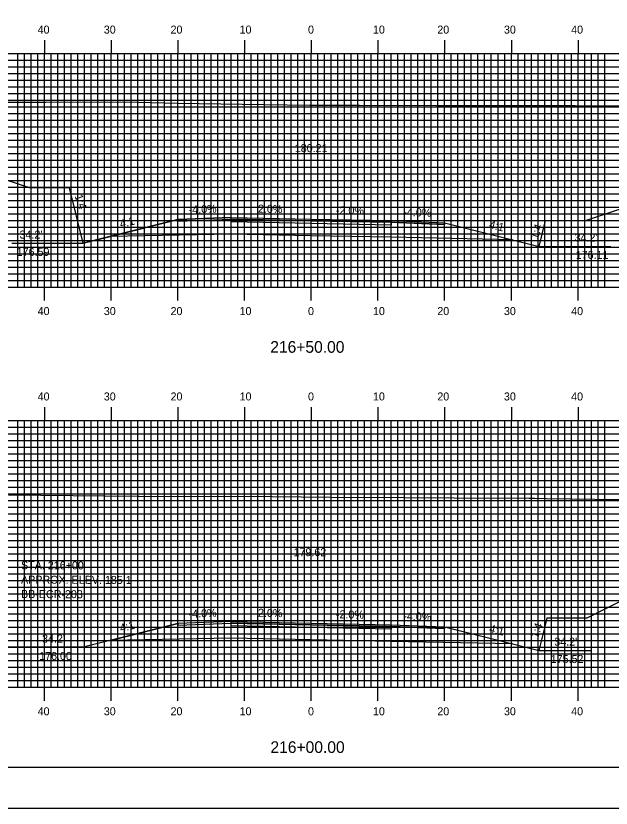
# Model space of a CAD drawing. Extents: x 1796420 to 1796763, y 442591 to 442811.
# Drawn here: x 1796541.6 to 1796630.9, y 442590.5 to 442709.3 of the extents above; entities that cross this region are included whole.
import ezdxf

# ---------------------------------------------------------------- set-up
doc = ezdxf.new("R2010")
doc.units = 0
for name, color, linetype in [('ANNOTATION', 7, 'Continuous'), ('BORDER', 7, 'Continuous'), ('BORING - REFUSAL', 7, 'Continuous'), ('D_Roadway_Centerline', 7, 'Continuous'), ('D_Roadway_Centerline_Text', 7, 'Continuous'), ('D_Roadway_Edge_Shoulder', 7, 'Continuous'), ('D_Roadway_Edge_TW', 7, 'Continuous'), ('D_Roadway_Pavement', 7, 'Continuous'), ('D_Roadway_SlopeLines', 7, 'Continuous'), ('D_Roadway_SubGrade', 7, 'Continuous'), ('H_V ANNOTATION', 7, 'Continuous'), ('MAJOR', 7, 'Continuous'), ('MINOR', 7, 'Continuous'), ('PDRAIN', 7, 'Continuous'), ('PLOT BOUNDARY', 7, 'Continuous'), ('S_Roadway_Centerline', 7, 'Continuous')]:
    doc.layers.add(name, color=color, linetype=linetype)

msp = doc.modelspace()

# ---------------------------------------------------------------- linework, layer by layer
at = {"layer": 'ANNOTATION'}
for p, q in [((1796620.08, 442674.77), (1796621.05, 442678.67)), ((1796620.08, 442614.19), (1796621.08, 442618.19)), ((1796551.73, 442614.67), (1796529.31, 442614.67))]:
    msp.add_line(p, q, dxfattribs=at)
at = {"layer": 'BORDER'}
msp.add_lwpolyline([(1796436.31, 442596.67), (1796756.31, 442596.67), (1796756.31, 442806.67), (1796436.31, 442806.67)], close=True, dxfattribs=at)
at = {"layer": 'D_Roadway_Centerline'}
msp.add_lwpolyline([(1796551.73, 442675.25), (1796555.73, 442676.25), (1796565.91, 442678.79), (1796573.91, 442679.11), (1796585.91, 442678.87), (1796597.91, 442678.63), (1796605.91, 442678.31), (1796616.08, 442675.77), (1796620.08, 442674.77)], dxfattribs=at)
at = {"layer": 'D_Roadway_Edge_Shoulder'}
for points in [[(1796573.91, 442679.11), (1796565.91, 442678.79), (1796565.91, 442678.54), (1796573.91, 442678.86)], [(1796597.91, 442678.63), (1796605.91, 442678.31), (1796605.91, 442678.06), (1796597.91, 442678.38)], [(1796573.91, 442618.53), (1796565.91, 442618.21), (1796565.91, 442617.96), (1796573.91, 442618.28)], [(1796597.91, 442618.05), (1796605.91, 442617.73), (1796605.91, 442617.48), (1796597.91, 442617.8)]]:
    msp.add_lwpolyline(points, close=True, dxfattribs=at)
at = {"layer": 'D_Roadway_Edge_TW'}
for points in [[(1796573.91, 442678.86), (1796573.91, 442679.11), (1796585.91, 442678.87), (1796597.91, 442678.63), (1796597.91, 442678.38), (1796585.91, 442678.62)], [(1796573.91, 442618.28), (1796573.91, 442618.53), (1796585.91, 442618.29), (1796597.91, 442618.05), (1796597.91, 442617.8), (1796585.91, 442618.04)]]:
    msp.add_lwpolyline(points, close=True, dxfattribs=at)
at = {"layer": 'D_Roadway_Pavement'}
for points in [[(1796573.91, 442678.45), (1796573.91, 442678.86), (1796585.91, 442678.62), (1796597.91, 442678.38), (1796597.91, 442677.97), (1796585.91, 442678.21)], [(1796573.91, 442617.86), (1796573.91, 442618.28), (1796585.91, 442618.04), (1796597.91, 442617.8), (1796597.91, 442617.38), (1796585.91, 442617.62)]]:
    msp.add_lwpolyline(points, close=True, dxfattribs=at)
at = {"layer": 'D_Roadway_SlopeLines'}
msp.add_line((1796551.73, 442675.25), (1796549.65, 442683.57), dxfattribs=at)
for points in [[(1796549.65, 442683.57), (1796543.65, 442683.57), (1796505.9, 442696.15)], [(1796621.05, 442678.67), (1796627.05, 442678.67), (1796674.72, 442694.55)], [(1796565.91, 442678.79), (1796551.73, 442675.25)], [(1796605.91, 442678.31), (1796620.08, 442674.77)], [(1796621.3, 442619.07), (1796627.3, 442619.07), (1796660.02, 442635.43)], [(1796565.91, 442618.21), (1796551.73, 442614.67)], [(1796605.91, 442617.73), (1796620.08, 442614.19)]]:
    msp.add_lwpolyline(points, dxfattribs=at)
at = {"layer": 'D_Roadway_SubGrade'}
msp.add_line((1796621.08, 442618.19), (1796621.3, 442619.07), dxfattribs=at)
for points in [[(1796573.91, 442676.61), (1796555.73, 442676.25), (1796565.91, 442678.79), (1796565.91, 442678.54), (1796573.91, 442678.86), (1796585.91, 442678.62), (1796597.91, 442678.38), (1796605.91, 442678.06), (1796605.91, 442678.31), (1796616.08, 442675.77), (1796597.91, 442676.13), (1796585.91, 442676.37)], [(1796573.91, 442616.03), (1796555.73, 442615.67), (1796565.91, 442618.21), (1796565.91, 442617.96), (1796573.91, 442618.28), (1796585.91, 442618.04), (1796597.91, 442617.8), (1796605.91, 442617.48), (1796605.91, 442617.73), (1796616.08, 442615.19), (1796597.91, 442615.55), (1796585.91, 442615.79)]]:
    msp.add_lwpolyline(points, close=True, dxfattribs=at)
at = {"layer": 'MAJOR'}
for p, q in [((1796545.91, 442705.67), (1796545.91, 442703.67)), ((1796555.91, 442705.67), (1796555.91, 442703.67)), ((1796565.91, 442705.67), (1796565.91, 442703.67)), ((1796575.91, 442705.67), (1796575.91, 442703.67)), ((1796585.91, 442705.67), (1796585.91, 442703.67)), ((1796595.91, 442705.67), (1796595.91, 442703.67)), ((1796605.91, 442705.67), (1796605.91, 442703.67)), ((1796615.91, 442705.67), (1796615.91, 442703.67)), ((1796625.91, 442705.67), (1796625.91, 442703.67)), ((1796445.91, 442703.67), (1796725.91, 442703.67)), ((1796445.91, 442703.67), (1796725.91, 442703.67)), ((1796545.91, 442668.67), (1796545.91, 442703.67)), ((1796555.91, 442668.67), (1796555.91, 442703.67)), ((1796565.91, 442668.67), (1796565.91, 442703.67)), ((1796575.91, 442668.67), (1796575.91, 442703.67)), ((1796585.91, 442668.67), (1796585.91, 442703.67)), ((1796595.91, 442668.67), (1796595.91, 442703.67)), ((1796605.91, 442668.67), (1796605.91, 442703.67)), ((1796615.91, 442668.67), (1796615.91, 442703.67)), ((1796625.91, 442668.67), (1796625.91, 442703.67)), ((1796445.91, 442698.67), (1796725.91, 442698.67)), ((1796445.91, 442693.67), (1796725.91, 442693.67)), ((1796445.91, 442688.67), (1796725.91, 442688.67)), ((1796445.91, 442683.67), (1796725.91, 442683.67)), ((1796445.91, 442678.67), (1796725.91, 442678.67)), ((1796445.91, 442673.67), (1796725.91, 442673.67)), ((1796445.91, 442668.67), (1796725.91, 442668.67)), ((1796445.91, 442668.67), (1796725.91, 442668.67)), ((1796545.91, 442666.66), (1796545.91, 442668.67)), ((1796555.91, 442666.66), (1796555.91, 442668.67)), ((1796565.91, 442666.66), (1796565.91, 442668.67)), ((1796575.91, 442666.66), (1796575.91, 442668.67)), ((1796585.91, 442666.66), (1796585.91, 442668.67)), ((1796595.91, 442666.66), (1796595.91, 442668.67)), ((1796605.91, 442666.66), (1796605.91, 442668.67)), ((1796615.91, 442666.66), (1796615.91, 442668.67)), ((1796625.91, 442666.66), (1796625.91, 442668.67)), ((1796545.91, 442650.67), (1796545.91, 442648.67)), ((1796555.91, 442650.67), (1796555.91, 442648.67)), ((1796565.91, 442650.67), (1796565.91, 442648.67)), ((1796575.91, 442650.67), (1796575.91, 442648.67)), ((1796585.91, 442650.67), (1796585.91, 442648.67)), ((1796595.91, 442650.67), (1796595.91, 442648.67)), ((1796605.91, 442650.67), (1796605.91, 442648.67)), ((1796615.91, 442650.67), (1796615.91, 442648.67)), ((1796625.91, 442650.67), (1796625.91, 442648.67)), ((1796445.91, 442648.67), (1796725.91, 442648.67)), ((1796445.91, 442648.67), (1796725.91, 442648.67)), ((1796545.91, 442608.67), (1796545.91, 442648.67)), ((1796555.91, 442608.67), (1796555.91, 442648.67)), ((1796565.91, 442608.67), (1796565.91, 442648.67)), ((1796575.91, 442608.67), (1796575.91, 442648.67)), ((1796585.91, 442608.67), (1796585.91, 442648.67)), ((1796595.91, 442608.67), (1796595.91, 442648.67)), ((1796605.91, 442608.67), (1796605.91, 442648.67)), ((1796615.91, 442608.67), (1796615.91, 442648.67)), ((1796625.91, 442608.67), (1796625.91, 442648.67)), ((1796445.91, 442643.67), (1796725.91, 442643.67)), ((1796445.91, 442638.67), (1796725.91, 442638.67)), ((1796445.91, 442633.67), (1796725.91, 442633.67)), ((1796445.91, 442628.67), (1796725.91, 442628.67)), ((1796445.91, 442623.67), (1796725.91, 442623.67)), ((1796445.91, 442618.67), (1796725.91, 442618.67)), ((1796445.91, 442613.67), (1796725.91, 442613.67)), ((1796445.91, 442608.67), (1796725.91, 442608.67)), ((1796445.91, 442608.67), (1796725.91, 442608.67)), ((1796545.91, 442606.66), (1796545.91, 442608.67)), ((1796555.91, 442606.66), (1796555.91, 442608.67)), ((1796565.91, 442606.66), (1796565.91, 442608.67)), ((1796575.91, 442606.66), (1796575.91, 442608.67)), ((1796585.91, 442606.66), (1796585.91, 442608.67)), ((1796595.91, 442606.66), (1796595.91, 442608.67)), ((1796605.91, 442606.66), (1796605.91, 442608.67)), ((1796615.91, 442606.66), (1796615.91, 442608.67)), ((1796625.91, 442606.66), (1796625.91, 442608.67))]:
    msp.add_line(p, q, dxfattribs=at)
at = {"layer": 'MINOR'}
for p, q in [((1796445.91, 442702.67), (1796725.91, 442702.67)), ((1796541.91, 442668.67), (1796541.91, 442703.67)), ((1796542.91, 442668.67), (1796542.91, 442703.67)), ((1796543.91, 442668.67), (1796543.91, 442703.67)), ((1796544.91, 442668.67), (1796544.91, 442703.67)), ((1796546.91, 442668.67), (1796546.91, 442703.67)), ((1796547.91, 442668.67), (1796547.91, 442703.67)), ((1796548.91, 442668.67), (1796548.91, 442703.67)), ((1796549.91, 442668.67), (1796549.91, 442703.67)), ((1796550.91, 442668.67), (1796550.91, 442703.67)), ((1796551.91, 442668.67), (1796551.91, 442703.67)), ((1796552.91, 442668.67), (1796552.91, 442703.67)), ((1796553.91, 442668.67), (1796553.91, 442703.67)), ((1796554.91, 442668.67), (1796554.91, 442703.67)), ((1796556.91, 442668.67), (1796556.91, 442703.67)), ((1796557.91, 442668.67), (1796557.91, 442703.67)), ((1796558.91, 442668.67), (1796558.91, 442703.67)), ((1796559.91, 442668.67), (1796559.91, 442703.67)), ((1796560.91, 442668.67), (1796560.91, 442703.67)), ((1796561.91, 442668.67), (1796561.91, 442703.67)), ((1796562.91, 442668.67), (1796562.91, 442703.67)), ((1796563.91, 442668.67), (1796563.91, 442703.67)), ((1796564.91, 442668.67), (1796564.91, 442703.67)), ((1796566.91, 442668.67), (1796566.91, 442703.67)), ((1796567.91, 442668.67), (1796567.91, 442703.67)), ((1796568.91, 442668.67), (1796568.91, 442703.67)), ((1796569.91, 442668.67), (1796569.91, 442703.67)), ((1796570.91, 442668.67), (1796570.91, 442703.67)), ((1796571.91, 442668.67), (1796571.91, 442703.67)), ((1796572.91, 442668.67), (1796572.91, 442703.67)), ((1796573.91, 442668.67), (1796573.91, 442703.67)), ((1796574.91, 442668.67), (1796574.91, 442703.67)), ((1796576.91, 442668.67), (1796576.91, 442703.67)), ((1796577.91, 442668.67), (1796577.91, 442703.67)), ((1796578.91, 442668.67), (1796578.91, 442703.67)), ((1796579.91, 442668.67), (1796579.91, 442703.67)), ((1796580.91, 442668.67), (1796580.91, 442703.67)), ((1796581.91, 442668.67), (1796581.91, 442703.67)), ((1796582.91, 442668.67), (1796582.91, 442703.67)), ((1796583.91, 442668.67), (1796583.91, 442703.67)), ((1796584.91, 442668.67), (1796584.91, 442703.67)), ((1796586.91, 442668.67), (1796586.91, 442703.67)), ((1796587.91, 442668.67), (1796587.91, 442703.67)), ((1796588.91, 442668.67), (1796588.91, 442703.67)), ((1796589.91, 442668.67), (1796589.91, 442703.67)), ((1796590.91, 442668.67), (1796590.91, 442703.67)), ((1796591.91, 442668.67), (1796591.91, 442703.67)), ((1796592.91, 442668.67), (1796592.91, 442703.67)), ((1796593.91, 442668.67), (1796593.91, 442703.67)), ((1796594.91, 442668.67), (1796594.91, 442703.67)), ((1796596.91, 442668.67), (1796596.91, 442703.67)), ((1796597.91, 442668.67), (1796597.91, 442703.67)), ((1796598.91, 442668.67), (1796598.91, 442703.67)), ((1796599.91, 442668.67), (1796599.91, 442703.67)), ((1796600.91, 442668.67), (1796600.91, 442703.67)), ((1796601.91, 442668.67), (1796601.91, 442703.67)), ((1796602.91, 442668.67), (1796602.91, 442703.67)), ((1796603.91, 442668.67), (1796603.91, 442703.67)), ((1796604.91, 442668.67), (1796604.91, 442703.67)), ((1796606.91, 442668.67), (1796606.91, 442703.67)), ((1796607.91, 442668.67), (1796607.91, 442703.67)), ((1796608.91, 442668.67), (1796608.91, 442703.67)), ((1796609.91, 442668.67), (1796609.91, 442703.67)), ((1796610.91, 442668.67), (1796610.91, 442703.67)), ((1796611.91, 442668.67), (1796611.91, 442703.67)), ((1796612.91, 442668.67), (1796612.91, 442703.67)), ((1796613.91, 442668.67), (1796613.91, 442703.67)), ((1796614.91, 442668.67), (1796614.91, 442703.67)), ((1796616.91, 442668.67), (1796616.91, 442703.67)), ((1796617.91, 442668.67), (1796617.91, 442703.67)), ((1796618.91, 442668.67), (1796618.91, 442703.67)), ((1796619.91, 442668.67), (1796619.91, 442703.67)), ((1796620.91, 442668.67), (1796620.91, 442703.67)), ((1796621.91, 442668.67), (1796621.91, 442703.67)), ((1796622.91, 442668.67), (1796622.91, 442703.67)), ((1796623.91, 442668.67), (1796623.91, 442703.67)), ((1796624.91, 442668.67), (1796624.91, 442703.67)), ((1796626.91, 442668.67), (1796626.91, 442703.67)), ((1796627.91, 442668.67), (1796627.91, 442703.67)), ((1796628.91, 442668.67), (1796628.91, 442703.67)), ((1796629.91, 442668.67), (1796629.91, 442703.67)), ((1796445.91, 442701.67), (1796725.91, 442701.67)), ((1796445.91, 442700.67), (1796725.91, 442700.67)), ((1796445.91, 442699.67), (1796725.91, 442699.67)), ((1796445.91, 442697.67), (1796725.91, 442697.67)), ((1796445.91, 442696.67), (1796725.91, 442696.67)), ((1796445.91, 442695.67), (1796725.91, 442695.67)), ((1796445.91, 442694.67), (1796725.91, 442694.67)), ((1796445.91, 442692.67), (1796725.91, 442692.67)), ((1796445.91, 442691.67), (1796725.91, 442691.67)), ((1796445.91, 442690.67), (1796725.91, 442690.67)), ((1796445.91, 442689.67), (1796725.91, 442689.67)), ((1796445.91, 442687.67), (1796725.91, 442687.67)), ((1796445.91, 442686.67), (1796725.91, 442686.67)), ((1796445.91, 442685.67), (1796725.91, 442685.67)), ((1796445.91, 442684.67), (1796725.91, 442684.67)), ((1796445.91, 442682.67), (1796725.91, 442682.67)), ((1796445.91, 442681.67), (1796725.91, 442681.67)), ((1796445.91, 442680.67), (1796725.91, 442680.67)), ((1796445.91, 442679.67), (1796725.91, 442679.67)), ((1796445.91, 442677.67), (1796725.91, 442677.67)), ((1796445.91, 442676.67), (1796725.91, 442676.67)), ((1796445.91, 442675.67), (1796725.91, 442675.67)), ((1796445.91, 442674.67), (1796725.91, 442674.67)), ((1796445.91, 442672.67), (1796725.91, 442672.67)), ((1796445.91, 442671.67), (1796725.91, 442671.67)), ((1796445.91, 442670.67), (1796725.91, 442670.67)), ((1796445.91, 442669.67), (1796725.91, 442669.67)), ((1796541.91, 442608.67), (1796541.91, 442648.67)), ((1796542.91, 442608.67), (1796542.91, 442648.67)), ((1796543.91, 442608.67), (1796543.91, 442648.67)), ((1796544.91, 442608.67), (1796544.91, 442648.67)), ((1796546.91, 442608.67), (1796546.91, 442648.67)), ((1796547.91, 442608.67), (1796547.91, 442648.67)), ((1796548.91, 442608.67), (1796548.91, 442648.67)), ((1796549.91, 442608.67), (1796549.91, 442648.67)), ((1796550.91, 442608.67), (1796550.91, 442648.67)), ((1796551.91, 442608.67), (1796551.91, 442648.67)), ((1796552.91, 442608.67), (1796552.91, 442648.67)), ((1796553.91, 442608.67), (1796553.91, 442648.67)), ((1796554.91, 442608.67), (1796554.91, 442648.67)), ((1796556.91, 442608.67), (1796556.91, 442648.67)), ((1796557.91, 442608.67), (1796557.91, 442648.67)), ((1796558.91, 442608.67), (1796558.91, 442648.67)), ((1796559.91, 442608.67), (1796559.91, 442648.67)), ((1796560.91, 442608.67), (1796560.91, 442648.67)), ((1796561.91, 442608.67), (1796561.91, 442648.67)), ((1796562.91, 442608.67), (1796562.91, 442648.67)), ((1796563.91, 442608.67), (1796563.91, 442648.67)), ((1796564.91, 442608.67), (1796564.91, 442648.67)), ((1796566.91, 442608.67), (1796566.91, 442648.67)), ((1796567.91, 442608.67), (1796567.91, 442648.67)), ((1796568.91, 442608.67), (1796568.91, 442648.67)), ((1796569.91, 442608.67), (1796569.91, 442648.67)), ((1796570.91, 442608.67), (1796570.91, 442648.67)), ((1796571.91, 442608.67), (1796571.91, 442648.67)), ((1796572.91, 442608.67), (1796572.91, 442648.67)), ((1796573.91, 442608.67), (1796573.91, 442648.67)), ((1796574.91, 442608.67), (1796574.91, 442648.67)), ((1796576.91, 442608.67), (1796576.91, 442648.67)), ((1796577.91, 442608.67), (1796577.91, 442648.67)), ((1796578.91, 442608.67), (1796578.91, 442648.67)), ((1796579.91, 442608.67), (1796579.91, 442648.67)), ((1796580.91, 442608.67), (1796580.91, 442648.67)), ((1796581.91, 442608.67), (1796581.91, 442648.67)), ((1796582.91, 442608.67), (1796582.91, 442648.67)), ((1796583.91, 442608.67), (1796583.91, 442648.67)), ((1796584.91, 442608.67), (1796584.91, 442648.67)), ((1796586.91, 442608.67), (1796586.91, 442648.67)), ((1796587.91, 442608.67), (1796587.91, 442648.67)), ((1796588.91, 442608.67), (1796588.91, 442648.67)), ((1796589.91, 442608.67), (1796589.91, 442648.67)), ((1796590.91, 442608.67), (1796590.91, 442648.67)), ((1796591.91, 442608.67), (1796591.91, 442648.67)), ((1796592.91, 442608.67), (1796592.91, 442648.67)), ((1796593.91, 442608.67), (1796593.91, 442648.67)), ((1796594.91, 442608.67), (1796594.91, 442648.67)), ((1796596.91, 442608.67), (1796596.91, 442648.67)), ((1796597.91, 442608.67), (1796597.91, 442648.67)), ((1796598.91, 442608.67), (1796598.91, 442648.67)), ((1796599.91, 442608.67), (1796599.91, 442648.67)), ((1796600.91, 442608.67), (1796600.91, 442648.67)), ((1796601.91, 442608.67), (1796601.91, 442648.67)), ((1796602.91, 442608.67), (1796602.91, 442648.67)), ((1796603.91, 442608.67), (1796603.91, 442648.67)), ((1796604.91, 442608.67), (1796604.91, 442648.67)), ((1796606.91, 442608.67), (1796606.91, 442648.67)), ((1796607.91, 442608.67), (1796607.91, 442648.67)), ((1796608.91, 442608.67), (1796608.91, 442648.67)), ((1796609.91, 442608.67), (1796609.91, 442648.67)), ((1796610.91, 442608.67), (1796610.91, 442648.67)), ((1796611.91, 442608.67), (1796611.91, 442648.67)), ((1796612.91, 442608.67), (1796612.91, 442648.67)), ((1796613.91, 442608.67), (1796613.91, 442648.67)), ((1796614.91, 442608.67), (1796614.91, 442648.67)), ((1796616.91, 442608.67), (1796616.91, 442648.67)), ((1796617.91, 442608.67), (1796617.91, 442648.67)), ((1796618.91, 442608.67), (1796618.91, 442648.67)), ((1796619.91, 442608.67), (1796619.91, 442648.67)), ((1796620.91, 442608.67), (1796620.91, 442648.67)), ((1796621.91, 442608.67), (1796621.91, 442648.67)), ((1796622.91, 442608.67), (1796622.91, 442648.67)), ((1796623.91, 442608.67), (1796623.91, 442648.67)), ((1796624.91, 442608.67), (1796624.91, 442648.67)), ((1796626.91, 442608.67), (1796626.91, 442648.67)), ((1796627.91, 442608.67), (1796627.91, 442648.67)), ((1796628.91, 442608.67), (1796628.91, 442648.67)), ((1796629.91, 442608.67), (1796629.91, 442648.67)), ((1796445.91, 442647.67), (1796725.91, 442647.67)), ((1796445.91, 442646.67), (1796725.91, 442646.67)), ((1796445.91, 442645.67), (1796725.91, 442645.67)), ((1796445.91, 442644.67), (1796725.91, 442644.67)), ((1796445.91, 442642.67), (1796725.91, 442642.67)), ((1796445.91, 442641.67), (1796725.91, 442641.67)), ((1796445.91, 442640.67), (1796725.91, 442640.67)), ((1796445.91, 442639.67), (1796725.91, 442639.67)), ((1796445.91, 442637.67), (1796725.91, 442637.67)), ((1796445.91, 442636.67), (1796725.91, 442636.67)), ((1796445.91, 442635.67), (1796725.91, 442635.67)), ((1796445.91, 442634.67), (1796725.91, 442634.67)), ((1796445.91, 442632.67), (1796725.91, 442632.67)), ((1796445.91, 442631.67), (1796725.91, 442631.67)), ((1796445.91, 442630.67), (1796725.91, 442630.67)), ((1796445.91, 442629.67), (1796725.91, 442629.67)), ((1796445.91, 442627.67), (1796725.91, 442627.67)), ((1796445.91, 442626.67), (1796725.91, 442626.67)), ((1796445.91, 442625.67), (1796725.91, 442625.67)), ((1796445.91, 442624.67), (1796725.91, 442624.67)), ((1796445.91, 442622.67), (1796725.91, 442622.67)), ((1796445.91, 442621.67), (1796725.91, 442621.67)), ((1796445.91, 442620.67), (1796725.91, 442620.67)), ((1796445.91, 442619.67), (1796725.91, 442619.67)), ((1796445.91, 442617.67), (1796725.91, 442617.67)), ((1796445.91, 442616.67), (1796725.91, 442616.67)), ((1796445.91, 442615.67), (1796725.91, 442615.67)), ((1796445.91, 442614.67), (1796725.91, 442614.67)), ((1796445.91, 442612.67), (1796725.91, 442612.67)), ((1796445.91, 442611.67), (1796725.91, 442611.67)), ((1796445.91, 442610.67), (1796725.91, 442610.67)), ((1796445.91, 442609.67), (1796725.91, 442609.67))]:
    msp.add_line(p, q, dxfattribs=at)
at = {"layer": 'PDRAIN'}
for p, q in [((1796541.01, 442675.25), (1796551.73, 442675.25)), ((1796620.08, 442674.77), (1796630.85, 442674.77)), ((1796544.38, 442614.67), (1796551.73, 442614.67)), ((1796620.08, 442614.19), (1796627.81, 442614.19))]:
    msp.add_line(p, q, dxfattribs=at)
at = {"layer": 'PLOT BOUNDARY'}
msp.add_lwpolyline([(1796420.12, 442590.55), (1796760.12, 442590.55), (1796760.12, 442810.55), (1796420.12, 442810.55)], close=True, dxfattribs=at)
at = {"layer": 'S_Roadway_Centerline'}
for points in [[(1796487.88, 442696.94), (1796498.86, 442696.78), (1796506.27, 442696.78), (1796517.15, 442696.43), (1796526.08, 442696.33), (1796533.98, 442696.39), (1796545.59, 442696.39), (1796546.1, 442696.39), (1796557.91, 442696.42), (1796565.89, 442696.24), (1796575.55, 442696.1), (1796585.62, 442695.94), (1796593.15, 442695.94), (1796604.73, 442695.91), (1796605.08, 442695.91), (1796605.32, 442695.91), (1796616.8, 442695.87), (1796625.5, 442695.88), (1796628.63, 442695.82), (1796633.06, 442695.87)], [(1796540.51, 442637.5), (1796559.84, 442637.32), (1796560.01, 442637.32), (1796560.04, 442637.32), (1796560.1, 442637.32), (1796580.05, 442637.25), (1796588.77, 442637.19), (1796599.82, 442637.13), (1796607.32, 442637.09), (1796618.56, 442637.03), (1796619.4, 442637.02), (1796621.2, 442636.99), (1796639.28, 442636.72)]]:
    msp.add_lwpolyline(points, dxfattribs=at)

# ---------------------------------------------------------------- texts
at = {"layer": 'ANNOTATION'}
for s, rotation, p in [('1:4', 289.484, (1796550.41, 442682.31)), ('-4.0%', 2.2906, (1796567.54, 442679.66)), ('2.0%', 358.8542, (1796577.91, 442679.83)), ('-2.0%', 358.8542, (1796589.59, 442679.6)), ('-4.0%', 357.7094, (1796599.7, 442679.36)), ('4:1', 14.0362, (1796557.35, 442677.52)), ('4:1', 345.9638, (1796612.5, 442677.53)), ('1:4', 70.516, (1796619.84, 442675.74)), ('-4.0%', 2.2906, (1796567.54, 442619.08)), ('2.0%', 358.8542, (1796577.91, 442619.25)), ('-2.0%', 358.8542, (1796589.59, 442619.02)), ('-4.0%', 357.7094, (1796599.7, 442618.78)), ('4:1', 14.0362, (1796557.35, 442616.93)), ('4:1', 345.9638, (1796612.5, 442616.94)), ('1:4', 70.516, (1796619.89, 442615.94))]:
    msp.add_text(s, height=1.2, rotation=rotation, dxfattribs=at).set_placement(p)
for s, p in [("34.2'", (1796542.17, 442675.94)), ("34.2'", (1796625.39, 442675.5)), ('176.59', (1796541.74, 442673.34)), ('176.11', (1796625.56, 442672.9)), ("34.2'", (1796545.54, 442615.36)), ("34.2'", (1796622.35, 442614.91)), ('176.00', (1796545.11, 442612.76)), ('175.52', (1796621.81, 442612.31))]:
    msp.add_text(s, height=1.2, dxfattribs=at).set_placement(p)
at = {"layer": 'BORING - REFUSAL'}
for s, p in [('STA. 216+00', (1796542.39, 442626.37)), ('APPROX. ELEV. 185.1', (1796542.39, 442624.21)), ('BB-ECR-203', (1796542.38, 442622.05))]:
    msp.add_text(s, height=1.2, rotation=359.8142, dxfattribs=at).set_placement(p)
at = {"layer": 'D_Roadway_Centerline'}
for s, p in [('C', (1796585.9, 442678.87)), ('L', (1796585.91, 442678.87)), ('C', (1796585.9, 442618.29)), ('L', (1796585.91, 442618.28))]:
    msp.add_text(s, height=0.0146, dxfattribs=at).set_placement(p)
at = {"layer": 'D_Roadway_Centerline_Text'}
for s, p in [('180.21', (1796583.44, 442688.9)), ('179.62', (1796583.25, 442628.32))]:
    msp.add_text(s, height=1.2, dxfattribs=at).set_placement(p)
at = {"layer": 'H_V ANNOTATION'}
for s, height, p in [('40', 1.2, (1796544.88, 442706.67)), ('30', 1.2, (1796554.8, 442706.67)), ('20', 1.2, (1796564.81, 442706.67)), ('10', 1.2, (1796575.16, 442706.67)), ('0', 1.2, (1796585.42, 442706.67)), ('10', 1.2, (1796595.16, 442706.67)), ('20', 1.2, (1796604.81, 442706.67)), ('30', 1.2, (1796614.8, 442706.67)), ('40', 1.2, (1796624.88, 442706.67)), ('40', 1.2, (1796544.88, 442664.47)), ('30', 1.2, (1796554.8, 442664.47)), ('20', 1.2, (1796564.81, 442664.47)), ('10', 1.2, (1796575.16, 442664.47)), ('0', 1.2, (1796585.42, 442664.47)), ('10', 1.2, (1796595.16, 442664.47)), ('20', 1.2, (1796604.81, 442664.47)), ('30', 1.2, (1796614.8, 442664.47)), ('40', 1.2, (1796624.88, 442664.47)), ('216+50.00', 1.75, (1796579.76, 442658.82)), ('40', 1.2, (1796544.88, 442651.67)), ('30', 1.2, (1796554.8, 442651.67)), ('20', 1.2, (1796564.81, 442651.67)), ('10', 1.2, (1796575.16, 442651.67)), ('0', 1.2, (1796585.42, 442651.67)), ('10', 1.2, (1796595.16, 442651.67)), ('20', 1.2, (1796604.81, 442651.67)), ('30', 1.2, (1796614.8, 442651.67)), ('40', 1.2, (1796624.88, 442651.67)), ('40', 1.2, (1796544.88, 442604.47)), ('30', 1.2, (1796554.8, 442604.47)), ('20', 1.2, (1796564.81, 442604.47)), ('10', 1.2, (1796575.16, 442604.47)), ('0', 1.2, (1796585.42, 442604.47)), ('10', 1.2, (1796595.16, 442604.47)), ('20', 1.2, (1796604.81, 442604.47)), ('30', 1.2, (1796614.8, 442604.47)), ('40', 1.2, (1796624.88, 442604.47)), ('216+00.00', 1.75, (1796579.79, 442598.82))]:
    msp.add_text(s, height=height, dxfattribs=at).set_placement(p)

doc.saveas('drawing.dxf')
